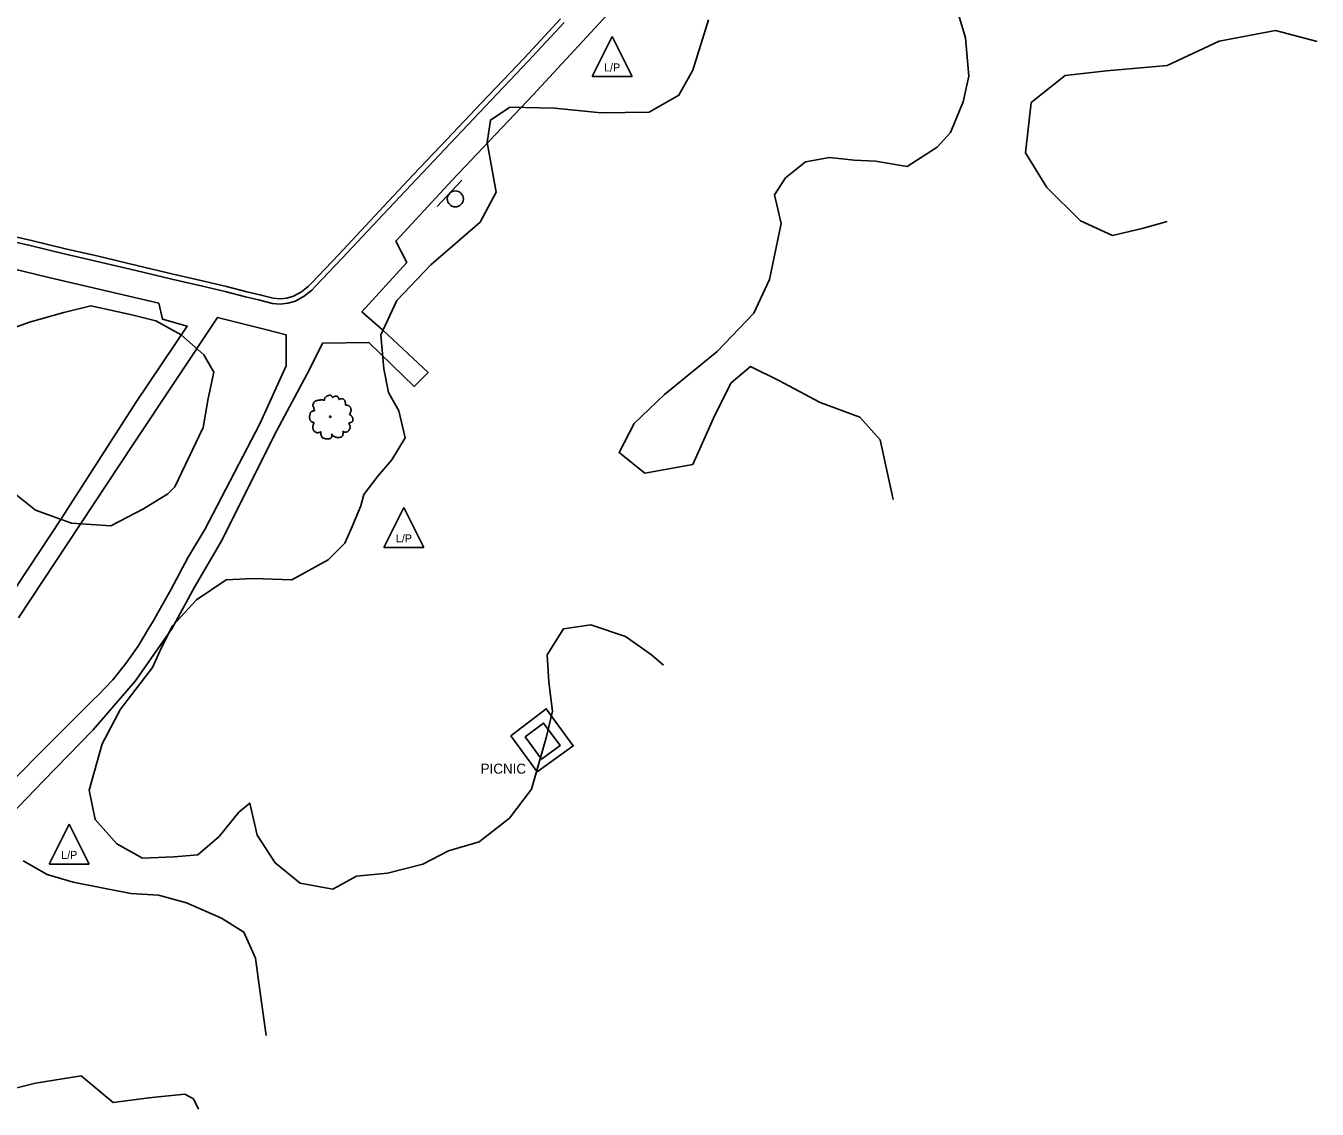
# Model space of a CAD drawing. Extents: x 2161152 to 2175754, y 602179 to 617749.
# Drawn here: x 2163512.2 to 2163834.9, y 605134.1 to 605404.6 of the extents above; entities that cross this region are included whole.
import ezdxf

# ---------------------------------------------------------------- set-up
doc = ezdxf.new("R2010")
doc.units = 0
for name, color, linetype in [('RD_EX_BldgApp_Sign', 7, 'Continuous'), ('RD_EX_Conc_Curb', 7, 'Continuous'), ('RD_EX_Conc_Gutter', 7, 'Continuous'), ('RD_EX_Conc_Sidewalk', 7, 'Continuous'), ('RD_EX_Conc_Slab', 7, 'Continuous'), ('RD_EX_Misc', 7, 'Continuous'), ('RD_EX_Misc_Golf_Cartpath', 7, 'Continuous'), ('RD_EX_UT', 7, 'Continuous'), ('RD_EX_VEG', 7, 'Continuous')]:
    doc.layers.add(name, color=color, linetype=linetype)

msp = doc.modelspace()

# ---------------------------------------------------------------- linework, layer by layer
at = {"layer": 'RD_EX_BldgApp_Sign'}
msp.add_line((2163621.15, 605366.06), (2163614.97, 605359.52), dxfattribs=at)
msp.add_circle((2163619.52, 605361.39), 2, dxfattribs=at)
at = {"layer": 'RD_EX_Conc_Curb'}
msp.add_lwpolyline([(2163505.13, 605351.59), (2163513.31, 605349.73), (2163521.82, 605347.7), (2163529.66, 605345.88), (2163539.67, 605343.53), (2163548.68, 605341.36), (2163556.38, 605339.61), (2163562.03, 605338.23), (2163567.08, 605336.95), (2163570.37, 605336.15), (2163573.81, 605335.3), (2163575.76, 605335.11), (2163577.7, 605335.31), (2163579.56, 605335.89), (2163579.69, 605335.95), (2163581.77, 605337.09), (2163583.64, 605338.57), (2163584.6, 605339.56), (2163591.24, 605346.57), (2163601.39, 605357.42), (2163609.96, 605366.5), (2163618.34, 605375.35), (2163626.99, 605384.46), (2163637.74, 605395.78), (2163646.73, 605405.44)], dxfattribs=at)
at = {"layer": 'RD_EX_Conc_Gutter'}
msp.add_lwpolyline([(2163505.42, 605352.85), (2163513.6, 605350.99), (2163522.12, 605348.96), (2163529.95, 605347.14), (2163539.97, 605344.79), (2163548.98, 605342.62), (2163556.67, 605340.87), (2163562.34, 605339.48), (2163567.39, 605338.21), (2163570.67, 605337.41), (2163574.03, 605336.58), (2163575.75, 605336.41), (2163577.44, 605336.58), (2163579.11, 605337.11), (2163581.05, 605338.18), (2163582.77, 605339.53), (2163583.66, 605340.46), (2163590.3, 605347.46), (2163600.45, 605358.31), (2163609.02, 605367.39), (2163617.4, 605376.24), (2163626.05, 605385.35), (2163636.8, 605396.66), (2163645.79, 605406.32)], dxfattribs=at)
at = {"layer": 'RD_EX_Conc_Sidewalk'}
for points in [[(2163661.55, 605411.87), (2163638.94, 605387.4), (2163618.72, 605366.07), (2163604.62, 605350.85), (2163607.38, 605345.49), (2163596.16, 605333.2), (2163601.34, 605328.65), (2163612.73, 605318), (2163609.21, 605314.57), (2163597.91, 605325.54), (2163586.34, 605325.35), (2163583.09, 605318.79), (2163574.36, 605302.44), (2163561.29, 605276.24), (2163554.35, 605264.41), (2163548.72, 605253.98), (2163539.55, 605240.93), (2163529.06, 605228.81), (2163516.51, 605215.95), (2163502.01, 605201.03)], [(2163502.79, 605345.39), (2163517.97, 605341.74), (2163532.98, 605338.27), (2163545.46, 605335.34)], [(2163545.46, 605335.34), (2163546.33, 605331.35), (2163552.52, 605329.59), (2163539.66, 605310.58), (2163521.19, 605281.76), (2163507.09, 605260.46)], [(2163510.37, 605256.75), (2163522.57, 605275.2), (2163539.1, 605300.18), (2163560.08, 605331.78), (2163571.76, 605328.85), (2163577.25, 605327.45), (2163577.27, 605319.74), (2163570.65, 605305.21), (2163556.9, 605278.85), (2163552.8, 605271.93), (2163548.51, 605263.89), (2163543.99, 605255.96), (2163542.95, 605254.19), (2163540.25, 605249.67), (2163537.23, 605245.37), (2163533.9, 605241.29), (2163530.27, 605237.48), (2163529.01, 605236.28), (2163520.92, 605228.18), (2163505.15, 605212.4)]]:
    msp.add_lwpolyline(points, dxfattribs=at)
at = {"layer": 'RD_EX_Conc_Slab'}
msp.add_lwpolyline([(2163633.36, 605227.26), (2163639.95, 605218.27), (2163648.99, 605224.77), (2163642.23, 605234.05), (2163633.36, 605227.26)], dxfattribs=at)
at = {"layer": 'RD_EX_Misc'}
msp.add_lwpolyline([(2163637, 605227.03), (2163641.08, 605221.47), (2163645.71, 605224.85), (2163641.57, 605230.47), (2163637, 605227.03)], dxfattribs=at)
at = {"layer": 'RD_EX_UT'}
for p, q in [((2163653.69, 605391.95), (2163658.69, 605401.95)), ((2163658.69, 605401.95), (2163663.69, 605391.95)), ((2163653.69, 605391.95), (2163663.69, 605391.95)), ((2163601.67, 605274.33), (2163606.67, 605284.33)), ((2163606.67, 605284.33), (2163611.67, 605274.33)), ((2163601.67, 605274.33), (2163611.67, 605274.33)), ((2163518.06, 605195.27), (2163523.06, 605205.27)), ((2163523.06, 605205.27), (2163528.06, 605195.27)), ((2163518.06, 605195.27), (2163528.06, 605195.27))]:
    msp.add_line(p, q, dxfattribs=at)
at = {"layer": 'RD_EX_VEG'}
for points in [[(2163742.91, 605415.33), (2163746.97, 605401.63), (2163747.79, 605392.01), (2163746.4, 605385.61), (2163743.24, 605377.99), (2163739.93, 605374.35), (2163732.38, 605369.49), (2163724.48, 605370.81), (2163719.17, 605371.05), (2163713.03, 605371.7), (2163706.99, 605370.65), (2163702.01, 605366.63), (2163699.23, 605362.44), (2163700.93, 605355.22), (2163698.01, 605341.25), (2163694.09, 605332.86), (2163684.9, 605323.24), (2163671.76, 605312.51), (2163664.22, 605305.27), (2163660.43, 605298.03), (2163666.85, 605292.87), (2163678.85, 605295.05), (2163684.34, 605307.39), (2163688.43, 605315.43), (2163693.29, 605319.56), (2163700.38, 605316.07), (2163710.68, 605310.52), (2163720.58, 605306.84), (2163725.71, 605301.22), (2163728.92, 605286.31)], [(2163671.55, 605244.97), (2163668.51, 605247.56), (2163662.01, 605252.1), (2163653.37, 605255.01), (2163646.58, 605254.06), (2163642.43, 605247.54), (2163642.84, 605240.69), (2163643.77, 605233.44), (2163642.19, 605226.81), (2163638.57, 605214.01), (2163633.09, 605206.77), (2163625.5, 605200.81), (2163617.79, 605198.55), (2163611.43, 605195.25), (2163602.57, 605193.02), (2163594.79, 605192.25), (2163588.93, 605188.98), (2163580.72, 605190.49), (2163574.5, 605195.59), (2163569.99, 605202.53), (2163568.16, 605210.49), (2163565.44, 605208.23), (2163560.49, 605202.16), (2163555.17, 605197.6), (2163549.28, 605197.12), (2163541.32, 605196.71), (2163534.94, 605200.32), (2163529.52, 605206.4), (2163528.05, 605213.75), (2163531.24, 605225.33), (2163535.85, 605233.99), (2163543.89, 605244.39), (2163546.12, 605249.32), (2163548.86, 605254.81), (2163554.87, 605261.29), (2163562.25, 605266.29), (2163569.03, 605266.63), (2163578.63, 605266.26), (2163587.78, 605271.29), (2163591.87, 605275.44), (2163593.56, 605279.12), (2163595.92, 605284.7), (2163596.67, 605287.57), (2163600.19, 605292.15), (2163603.62, 605296.21), (2163606.98, 605301.68), (2163605.38, 605308.47), (2163602.83, 605313.01), (2163601.66, 605318.94), (2163600.92, 605327.43), (2163604.92, 605336.05), (2163613.39, 605344.93), (2163625.69, 605355.61), (2163629.7, 605363.04), (2163627.45, 605375.51), (2163628.28, 605381.07), (2163633.11, 605384.28), (2163644.32, 605384.06), (2163655.96, 605382.9), (2163667.91, 605383.08), (2163675.4, 605387.28), (2163678.9, 605393.57), (2163682.75, 605406.09)], [(2163797.38, 605355.75), (2163791.12, 605353.97), (2163783.7, 605352.23), (2163775.72, 605355.94), (2163767.3, 605364.25), (2163761.97, 605372.93), (2163763.43, 605385.45), (2163771.88, 605392.21), (2163782.21, 605393.4), (2163797.36, 605394.71), (2163810.38, 605400.76), (2163824.46, 605403.46), (2163834.86, 605400.68)], [(2163505.42, 605327.86), (2163513.14, 605330.64), (2163521.66, 605333.04), (2163528.46, 605334.65), (2163538.73, 605332.41), (2163544.71, 605330.92), (2163551, 605327.41), (2163556.72, 605322.46), (2163559.21, 605318.14), (2163557.73, 605311.51), (2163556.55, 605304.33), (2163549.46, 605289.51)], [(2163549.46, 605289.51), (2163547.67, 605287.75), (2163541.58, 605283.97), (2163533.4, 605279.78), (2163523.63, 605280.39), (2163514.6, 605283.62), (2163509.18, 605287.95)], [(2163511.54, 605196.05), (2163517.56, 605192.67), (2163524.03, 605190.78), (2163531.22, 605189.32), (2163538.43, 605187.95), (2163545.33, 605187.51), (2163552.35, 605185.59), (2163561.1, 605181.76), (2163566.68, 605178.29), (2163569.61, 605171.81), (2163570.59, 605164.35), (2163572.25, 605152.46)], [(2163555.38, 605134.06), (2163554.08, 605136.63), (2163551.97, 605137.77), (2163542.94, 605136.93), (2163534.04, 605135.71), (2163526.04, 605142.39), (2163514.64, 605140.59), (2163501.77, 605137.41)]]:
    msp.add_lwpolyline(points, dxfattribs=at)
for centre, radius in [((2163588.26, 605306.98), 0.188), ((2163588.25, 605306.97), 0.000075)]:
    msp.add_circle(centre, radius, dxfattribs=at)
for points in [[(2163588.36, 605312.36), (2163588.13, 605312.38), (2163587.89, 605312.3), (2163587.7, 605312.23), (2163587.53, 605312.17), (2163587.37, 605312.09), (2163587.14, 605311.96), (2163586.97, 605311.81), (2163586.88, 605311.63), (2163586.84, 605311.46), (2163586.8, 605311.25), (2163586.8, 605311.12), (2163586.71, 605311.1), (2163586.6, 605311.12), (2163586.41, 605311.18), (2163586.22, 605311.18), (2163586.04, 605311.18), (2163585.77, 605311.16), (2163585.51, 605311.16), (2163585.3, 605311.12), (2163585.06, 605311.08), (2163584.78, 605310.99), (2163584.52, 605310.9), (2163584.29, 605310.71), (2163584.11, 605310.35), (2163584.01, 605310.09), (2163583.9, 605309.9), (2163584.01, 605309.56), (2163584.14, 605309.3), (2163584.16, 605309.15), (2163584.22, 605308.83), (2163584.29, 605308.67), (2163584.39, 605308.52), (2163584.33, 605308.5), (2163584.05, 605308.46), (2163583.82, 605308.38), (2163583.51, 605308.22), (2163583.34, 605308.05), (2163583.26, 605307.8), (2163583.24, 605307.54), (2163583.17, 605307.39), (2163583.11, 605307.18), (2163583.09, 605307.13), (2163583.06, 605306.88), (2163583.13, 605306.55), (2163583.15, 605306.28), (2163583.24, 605306.12), (2163583.36, 605305.99), (2163583.49, 605305.8), (2163583.79, 605305.63), (2163584.03, 605305.55), (2163584.18, 605305.54), (2163584.05, 605305.16), (2163584.01, 605304.9), (2163583.92, 605304.6), (2163583.92, 605304.54), (2163583.88, 605304.19), (2163583.99, 605303.94), (2163584.05, 605303.66), (2163584.18, 605303.49), (2163584.39, 605303.27), (2163584.63, 605303.1), (2163585, 605303.01), (2163585.3, 605303.02), (2163585.74, 605303.16), (2163585.92, 605303.21), (2163585.9, 605303.08), (2163585.92, 605302.8), (2163585.92, 605302.48), (2163586.04, 605302.24), (2163586.11, 605302.03), (2163586.22, 605301.84), (2163586.47, 605301.67), (2163586.77, 605301.62), (2163587.09, 605301.51), (2163587.42, 605301.45), (2163587.8, 605301.43), (2163588.25, 605301.54), (2163588.45, 605301.64), (2163588.53, 605301.77), (2163588.68, 605302.05), (2163588.64, 605302.22), (2163588.66, 605302.67), (2163588.73, 605302.54), (2163588.87, 605302.27), (2163589.24, 605302.05), (2163589.54, 605301.92), (2163589.9, 605301.81), (2163590.12, 605301.75), (2163590.48, 605301.81), (2163590.76, 605301.86), (2163591.04, 605301.96), (2163591.26, 605302.16), (2163591.4, 605302.37), (2163591.43, 605302.57), (2163591.49, 605302.86), (2163591.53, 605302.99)], [(2163591.53, 605302.99), (2163591.47, 605303.12), (2163591.43, 605303.3), (2163591.49, 605303.29), (2163591.62, 605303.25), (2163591.83, 605303.16), (2163592, 605303.1), (2163592.24, 605303.12), (2163592.45, 605303.19), (2163592.78, 605303.4), (2163592.99, 605303.75), (2163593.19, 605304.05), (2163593.25, 605304.3), (2163593.21, 605304.47), (2163593.19, 605304.84), (2163593.04, 605305.03), (2163593.01, 605305.12), (2163592.93, 605305.42), (2163592.99, 605305.46), (2163593.19, 605305.5), (2163593.48, 605305.59), (2163593.68, 605305.69), (2163593.85, 605305.82), (2163593.91, 605305.99), (2163593.89, 605306.28), (2163593.93, 605306.58), (2163593.87, 605306.7), (2163593.79, 605306.81), (2163593.74, 605306.96), (2163593.63, 605307.07), (2163593.55, 605307.18), (2163593.48, 605307.26), (2163593.38, 605307.37), (2163593.25, 605307.47), (2163593.14, 605307.5), (2163593.1, 605307.62), (2163593.21, 605307.77), (2163593.25, 605307.84), (2163593.27, 605308.01), (2163593.44, 605308.27), (2163593.48, 605308.57), (2163593.44, 605308.89), (2163593.4, 605309.1), (2163593.29, 605309.3), (2163593.14, 605309.49), (2163593.04, 605309.62), (2163592.91, 605309.71), (2163592.67, 605309.81), (2163592.48, 605309.85), (2163592.22, 605309.85), (2163592.07, 605309.88), (2163592.09, 605309.92), (2163592.09, 605310.03), (2163592.09, 605310.24), (2163592.03, 605310.58), (2163591.92, 605310.95), (2163591.92, 605310.97), (2163591.85, 605311.16), (2163591.68, 605311.31), (2163591.55, 605311.38), (2163591.4, 605311.48), (2163591.21, 605311.5), (2163590.98, 605311.5), (2163590.78, 605311.46), (2163590.63, 605311.38), (2163590.5, 605311.29), (2163590.44, 605311.4), (2163590.36, 605311.63), (2163590.33, 605311.74), (2163590.21, 605311.87), (2163590.05, 605312.02), (2163589.71, 605312.11), (2163589.24, 605312.06), (2163589.02, 605311.91), (2163588.9, 605311.78), (2163588.87, 605311.87), (2163588.72, 605312.02), (2163588.64, 605312.15), (2163588.51, 605312.24), (2163588.4, 605312.32), (2163588.32, 605312.36)]]:
    msp.add_spline(points, degree=3, dxfattribs=at)

# ---------------------------------------------------------------- texts
at = {"layer": 'RD_EX_Misc_Golf_Cartpath'}
msp.add_text('PICNIC', height=2.5, dxfattribs=at).set_placement((2163625.85, 605217.85))
at = {"layer": 'RD_EX_UT'}
for p in [(2163656.68, 605393.23), (2163604.67, 605275.61), (2163521.05, 605196.55)]:
    msp.add_text('L/P', height=2, dxfattribs=at).set_placement(p)

doc.saveas('drawing.dxf')
